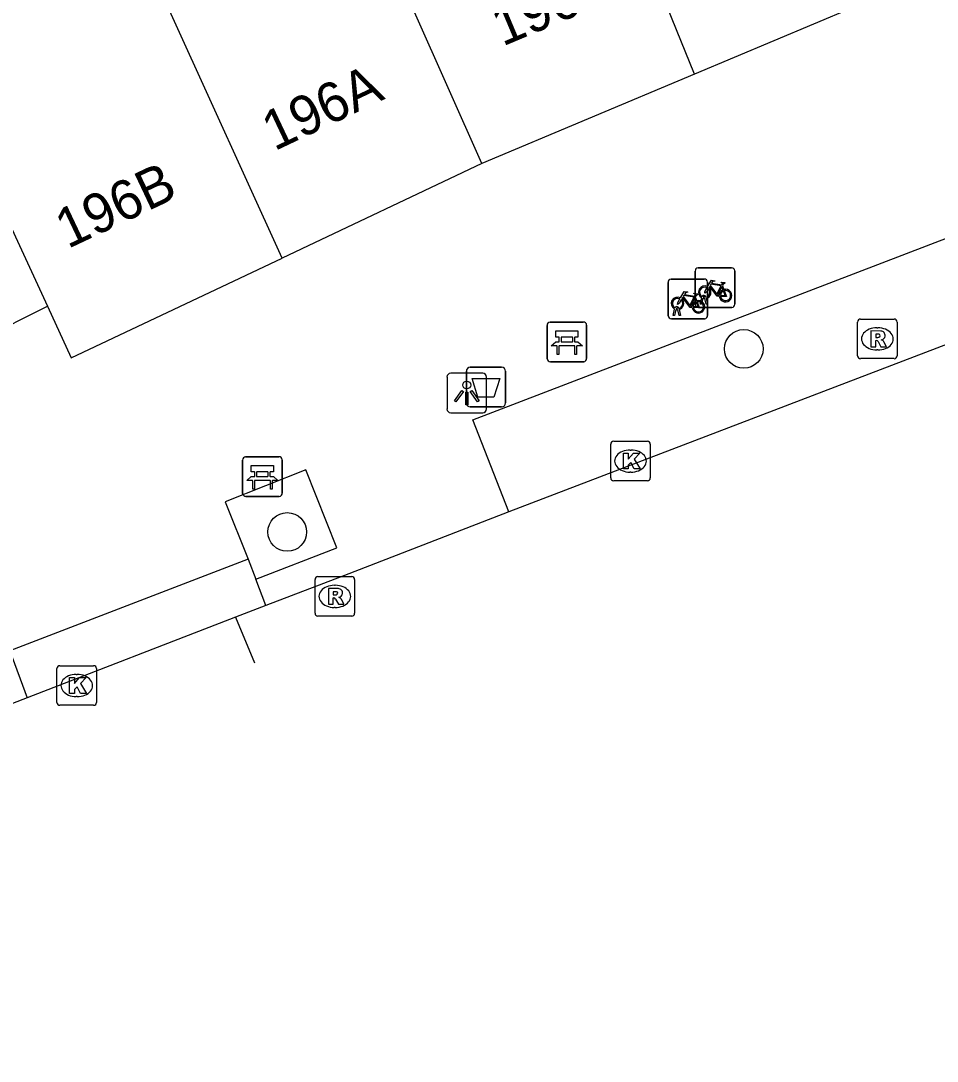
# Model space of a CAD drawing. Extents: x 159265 to 160143, y 383413 to 384319.
# Drawn here: x 159613.82 to 159636.98, y 383551.19 to 383577.48 of the extents above; entities that cross this region are included whole.
import ezdxf

# ---------------------------------------------------------------- set-up
doc = ezdxf.new("R2010")
doc.units = 0
for name, color, linetype in [('IMGEO_Afvalbak', 7, 'Continuous'), ('IMGEO_Bank', 7, 'Continuous'), ('IMGEO_Boom', 7, 'Continuous'), ('IMGEO_Fietsenrek', 7, 'Continuous'), ('IMGEO_Kolk', 7, 'Continuous'), ('IMGEO_Lichtpunt', 7, 'Continuous'), ('IMGEO_Pand', 7, 'Continuous'), ('IMGEO_Pand_nummerreeks', 7, 'Continuous'), ('IMGEO_Rijbaan_lokaal_gesloten', 7, 'Continuous'), ('IMGEO_Rijbaan_lokaal_open', 7, 'Continuous'), ('IMGEO_Rioolput', 7, 'Continuous'), ('IMGEO_Voetpad_open', 7, 'Continuous')]:
    doc.layers.add(name, color=color, linetype=linetype)

msp = doc.modelspace()

# ---------------------------------------------------------------- linework, layer by layer
at = {"layer": 'IMGEO_Afvalbak'}
for p, q in [((159625.079, 383567.826), (159625.079, 383568.626)), ((159625.079, 383568.626), (159625.079, 383567.826)), ((159625.179, 383568.726), (159625.969, 383568.726)), ((159625.969, 383568.726), (159625.179, 383568.726)), ((159626.069, 383568.626), (159626.069, 383567.826)), ((159626.069, 383567.826), (159626.069, 383568.626)), ((159625.969, 383567.726), (159625.179, 383567.726)), ((159625.179, 383567.726), (159625.969, 383567.726))]:
    msp.add_line(p, q, dxfattribs=at)
msp.add_lwpolyline([(159625.222, 383568.44), (159625.926, 383568.44), (159625.777, 383567.97), (159625.371, 383567.97), (159625.222, 383568.44)], dxfattribs=at)
for centre, start, end in [((159625.179, 383568.626), 90, 180), ((159625.179, 383568.626), 90, 180), ((159625.969, 383568.626), 0, 90), ((159625.969, 383568.626), 360, 90), ((159625.179, 383567.826), 180, 270), ((159625.179, 383567.826), 180, 270), ((159625.969, 383567.826), 270, 0), ((159625.969, 383567.826), 270, 0)]:
    msp.add_arc(centre, 0.1, start, end, dxfattribs=at)
at = {"layer": 'IMGEO_Bank'}
for p, q in [((159627.12, 383568.942), (159627.12, 383569.783)), ((159627.12, 383569.783), (159627.12, 383568.942)), ((159627.195, 383569.867), (159628.036, 383569.867)), ((159628.036, 383569.867), (159627.195, 383569.867)), ((159628.12, 383569.792), (159628.12, 383568.951)), ((159628.12, 383568.951), (159628.12, 383569.792)), ((159627.429, 383569.373), (159627.429, 383569.479)), ((159627.473, 383569.479), (159627.473, 383569.373)), ((159627.761, 383569.485), (159627.479, 383569.485)), ((159627.767, 383569.373), (159627.767, 383569.479)), ((159627.811, 383569.479), (159627.811, 383569.373)), ((159627.817, 383569.265), (159627.424, 383569.265)), ((159627.479, 383569.367), (159627.761, 383569.367)), ((159628.045, 383568.867), (159627.204, 383568.867)), ((159627.204, 383568.867), (159628.045, 383568.867)), ((159619.424, 383565.538), (159619.424, 383566.379)), ((159619.424, 383566.379), (159619.424, 383565.538)), ((159619.499, 383566.463), (159620.34, 383566.463)), ((159620.34, 383566.463), (159619.499, 383566.463)), ((159620.424, 383566.388), (159620.424, 383565.547)), ((159620.424, 383565.547), (159620.424, 383566.388)), ((159619.733, 383565.969), (159619.733, 383566.075)), ((159619.777, 383566.075), (159619.777, 383565.969)), ((159620.065, 383566.081), (159619.783, 383566.081)), ((159619.783, 383565.963), (159620.065, 383565.963)), ((159620.071, 383565.969), (159620.071, 383566.075)), ((159620.115, 383566.075), (159620.115, 383565.969)), ((159620.121, 383565.861), (159619.728, 383565.861)), ((159620.349, 383565.463), (159619.508, 383565.463)), ((159619.508, 383565.463), (159620.349, 383565.463))]:
    msp.add_line(p, q, dxfattribs=at)
for points in [[(159627.423, 383569.485), (159627.337, 383569.485), (159627.337, 383569.646), (159627.9, 383569.646), (159627.9, 383569.485), (159627.817, 383569.485)], [(159627.367, 383569.265), (159627.225, 383569.265), (159627.337, 383569.367), (159627.423, 383569.367)], [(159627.417, 383569.258), (159627.417, 383569.051), (159627.374, 383569.051), (159627.374, 383569.258)], [(159627.817, 383569.367), (159627.9, 383569.367), (159628.012, 383569.265), (159627.873, 383569.265)], [(159627.867, 383569.258), (159627.867, 383569.051), (159627.823, 383569.051), (159627.823, 383569.258)], [(159619.727, 383566.081), (159619.641, 383566.081), (159619.641, 383566.242), (159620.204, 383566.242), (159620.204, 383566.081), (159620.121, 383566.081)], [(159619.671, 383565.861), (159619.529, 383565.861), (159619.641, 383565.963), (159619.727, 383565.963)], [(159620.121, 383565.963), (159620.204, 383565.963), (159620.316, 383565.861), (159620.177, 383565.861)], [(159619.721, 383565.854), (159619.721, 383565.647), (159619.678, 383565.647), (159619.678, 383565.854)], [(159620.171, 383565.854), (159620.171, 383565.647), (159620.127, 383565.647), (159620.127, 383565.854)]]:
    msp.add_lwpolyline(points, dxfattribs=at)
for centre, radius, start, end in [((159627.198, 383569.789), 0.0779, 92.4484, 184.2845), ((159627.198, 383569.789), 0.0779, 92.4484, 184.2845), ((159628.042, 383569.789), 0.0779, 2.4484, 94.2845), ((159628.042, 383569.789), 0.0779, 2.4484, 94.2845), ((159627.422, 383569.478), 0.00671, 2.8957, 87.1043), ((159627.422, 383569.374), 0.00671, 272.8957, 357.1043), ((159627.479, 383569.478), 0.00671, 92.8957, 177.1043), ((159627.479, 383569.374), 0.00671, 182.8957, 267.1043), ((159627.761, 383569.478), 0.00671, 2.8957, 87.1043), ((159627.761, 383569.374), 0.00671, 272.8957, 357.1043), ((159627.818, 383569.478), 0.00671, 92.8957, 177.1043), ((159627.818, 383569.374), 0.00671, 182.8957, 267.1043), ((159627.367, 383569.258), 0.00671, 2.8957, 87.1043), ((159627.424, 383569.258), 0.00671, 92.8957, 177.1043), ((159627.816, 383569.258), 0.00671, 2.8957, 87.1043), ((159627.873, 383569.258), 0.00671, 92.8957, 177.1043), ((159627.198, 383568.945), 0.0779, 182.4484, 274.2845), ((159627.198, 383568.945), 0.0779, 182.4484, 274.2845), ((159628.042, 383568.945), 0.0779, 272.4484, 4.2845), ((159628.042, 383568.945), 0.0779, 272.4484, 4.2845), ((159619.502, 383566.385), 0.0779, 92.4484, 184.2845), ((159619.502, 383566.385), 0.0779, 92.4484, 184.2845), ((159620.346, 383566.385), 0.0779, 2.4484, 94.2845), ((159620.346, 383566.385), 0.0779, 2.4484, 94.2845), ((159619.726, 383566.074), 0.00671, 2.8957, 87.1043), ((159619.726, 383565.97), 0.00671, 272.8957, 357.1043), ((159619.783, 383566.074), 0.00671, 92.8957, 177.1043), ((159619.783, 383565.97), 0.00671, 182.8957, 267.1043), ((159620.065, 383566.074), 0.00671, 2.8957, 87.1043), ((159620.065, 383565.97), 0.00671, 272.8957, 357.1043), ((159620.122, 383566.074), 0.00671, 92.8957, 177.1043), ((159620.122, 383565.97), 0.00671, 182.8957, 267.1043), ((159619.671, 383565.854), 0.00671, 2.8957, 87.1043), ((159619.728, 383565.854), 0.00671, 92.8957, 177.1043), ((159620.12, 383565.854), 0.00671, 2.8957, 87.1043), ((159620.177, 383565.854), 0.00671, 92.8957, 177.1043), ((159619.502, 383565.541), 0.0779, 182.4484, 274.2845), ((159619.502, 383565.541), 0.0779, 182.4484, 274.2845), ((159620.346, 383565.541), 0.0779, 272.4484, 4.2845), ((159620.346, 383565.541), 0.0779, 272.4484, 4.2845)]:
    msp.add_arc(centre, radius, start, end, dxfattribs=at)
at = {"layer": 'IMGEO_Boom'}
for centre in [(159632.092, 383569.191), (159620.551, 383564.563)]:
    msp.add_circle(centre, 0.489, dxfattribs=at)
at = {"layer": 'IMGEO_Fietsenrek'}
for p, q in [((159630.939, 383571.238), (159631.78, 383571.238)), ((159631.78, 383571.238), (159630.939, 383571.238)), ((159630.253, 383570.954), (159631.094, 383570.954)), ((159631.094, 383570.954), (159630.253, 383570.954)), ((159630.864, 383570.313), (159630.864, 383571.154)), ((159630.864, 383571.154), (159630.864, 383570.313)), ((159631.864, 383571.163), (159631.864, 383570.322)), ((159631.864, 383570.322), (159631.864, 383571.163)), ((159630.178, 383570.029), (159630.178, 383570.87)), ((159630.178, 383570.87), (159630.178, 383570.029)), ((159631.178, 383570.879), (159631.178, 383570.038)), ((159631.178, 383570.038), (159631.178, 383570.879)), ((159631.551, 383570.787), (159631.587, 383570.692)), ((159630.865, 383570.503), (159630.901, 383570.408)), ((159630.991, 383570.322), (159631.03, 383570.482)), ((159631.06, 383570.47), (159631.025, 383570.322)), ((159631.102, 383570.494), (159631.101, 383570.498)), ((159631.143, 383570.322), (159631.109, 383570.464)), ((159631.133, 383570.505), (159631.134, 383570.498)), ((159631.141, 383570.468), (159631.176, 383570.322)), ((159630.305, 383570.038), (159630.344, 383570.198)), ((159630.374, 383570.186), (159630.339, 383570.038)), ((159630.416, 383570.21), (159630.415, 383570.214)), ((159630.457, 383570.038), (159630.423, 383570.18)), ((159630.447, 383570.221), (159630.448, 383570.214)), ((159630.455, 383570.184), (159630.49, 383570.038)), ((159631.789, 383570.238), (159630.948, 383570.238)), ((159630.948, 383570.238), (159631.789, 383570.238)), ((159631.025, 383570.322), (159630.991, 383570.322)), ((159631.176, 383570.322), (159631.143, 383570.322)), ((159631.103, 383569.954), (159630.262, 383569.954)), ((159630.262, 383569.954), (159631.103, 383569.954)), ((159630.339, 383570.038), (159630.305, 383570.038)), ((159630.49, 383570.038), (159630.457, 383570.038))]:
    msp.add_line(p, q, dxfattribs=at)
for points in [[(159631.198, 383570.712), (159631.146, 383570.622), (159631.106, 383570.597), (159631.107, 383570.644), (159631.162, 383570.738)], [(159631.177, 383570.764), (159631.272, 383570.928), (159631.358, 383570.914), (159631.36, 383570.905), (159631.304, 383570.894), (159631.277, 383570.849), (159631.533, 383570.808)], [(159631.473, 383570.52), (159631.423, 383570.52), (159631.232, 383570.771), (159631.213, 383570.739)], [(159631.52, 383570.783), (159631.263, 383570.824), (159631.246, 383570.795), (159631.413, 383570.575), (159631.52, 383570.783)], [(159631.568, 383570.685), (159631.538, 383570.762), (159631.429, 383570.544), (159631.472, 383570.544)], [(159631.533, 383570.808), (159631.558, 383570.857), (159631.552, 383570.861), (159631.529, 383570.865), (159631.517, 383570.872), (159631.516, 383570.875), (159631.518, 383570.88), (159631.613, 383570.865), (159631.615, 383570.855), (159631.605, 383570.842), (159631.593, 383570.836), (159631.579, 383570.842), (159631.551, 383570.787)], [(159630.512, 383570.428), (159630.46, 383570.338), (159630.42, 383570.313), (159630.421, 383570.36), (159630.476, 383570.454)], [(159630.491, 383570.48), (159630.586, 383570.644), (159630.672, 383570.63), (159630.674, 383570.621), (159630.618, 383570.61), (159630.591, 383570.565), (159630.847, 383570.524)], [(159630.787, 383570.236), (159630.737, 383570.236), (159630.546, 383570.487), (159630.527, 383570.455)], [(159630.834, 383570.499), (159630.577, 383570.54), (159630.56, 383570.511), (159630.727, 383570.291), (159630.834, 383570.499)], [(159630.882, 383570.401), (159630.852, 383570.478), (159630.743, 383570.26), (159630.786, 383570.26)], [(159630.847, 383570.524), (159630.872, 383570.573), (159630.866, 383570.577), (159630.843, 383570.581), (159630.831, 383570.588), (159630.83, 383570.591), (159630.832, 383570.596), (159630.927, 383570.581), (159630.929, 383570.571), (159630.919, 383570.558), (159630.907, 383570.552), (159630.893, 383570.558), (159630.865, 383570.503)], [(159631.502, 383570.544), (159631.622, 383570.543), (159631.578, 383570.657)], [(159631.598, 383570.664), (159631.653, 383570.519), (159631.503, 383570.519)], [(159630.816, 383570.26), (159630.936, 383570.259), (159630.892, 383570.373)], [(159630.912, 383570.38), (159630.967, 383570.235), (159630.817, 383570.235)]]:
    msp.add_lwpolyline(points, dxfattribs=at)
for centre, radius, start, end in [((159630.942, 383571.16), 0.0779, 92.4484, 184.2845), ((159630.942, 383571.16), 0.0779, 92.4484, 184.2845), ((159631.786, 383571.16), 0.0779, 2.4484, 94.2845), ((159631.786, 383571.16), 0.0779, 2.4484, 94.2845), ((159630.256, 383570.876), 0.0779, 92.4484, 184.2845), ((159630.256, 383570.876), 0.0779, 92.4484, 184.2845), ((159631.1, 383570.876), 0.0779, 2.4484, 94.2845), ((159631.1, 383570.876), 0.0779, 2.4484, 94.2845), ((159631.104, 383570.623), 0.159, 62.6766, 242.1369), ((159631.104, 383570.623), 0.129, 63.3192, 238.903), ((159631.104, 383570.623), 0.129, 283.6043, 43.4302), ((159631.104, 383570.623), 0.159, 283.5766, 46.6042), ((159631.631, 383570.539), 0.159, 187.0065, 105.7708), ((159630.418, 383570.339), 0.159, 62.6766, 242.1369), ((159630.418, 383570.339), 0.129, 63.3192, 238.903), ((159630.418, 383570.339), 0.129, 283.6043, 43.4302), ((159630.418, 383570.339), 0.159, 283.5766, 46.6042), ((159631.084, 383570.494), 0.0499, 12.8025, 158.6934), ((159631.104, 383570.623), 0.159, 253.9967, 271.7867), ((159631.084, 383570.494), 0.0174, 12.8025, 163.4502), ((159631.104, 383570.623), 0.129, 253.415, 269.0204), ((159631.631, 383570.539), 0.159, 113.3408, 178.3217), ((159631.631, 383570.539), 0.129, 113.923, 177.9556), ((159631.631, 383570.539), 0.129, 188.6715, 104.5883), ((159630.398, 383570.21), 0.0499, 12.8025, 158.6934), ((159630.418, 383570.339), 0.159, 253.9967, 271.7867), ((159630.398, 383570.21), 0.0174, 12.8025, 163.4502), ((159630.418, 383570.339), 0.129, 253.415, 269.0204), ((159630.945, 383570.255), 0.159, 113.3408, 178.3217), ((159630.945, 383570.255), 0.159, 187.0065, 105.7708), ((159630.945, 383570.255), 0.129, 113.923, 177.9556), ((159630.945, 383570.255), 0.129, 188.6715, 104.5883), ((159630.942, 383570.316), 0.0779, 182.4484, 274.2845), ((159630.942, 383570.316), 0.0779, 182.4484, 274.2845), ((159631.786, 383570.316), 0.0779, 272.4484, 4.2845), ((159631.786, 383570.316), 0.0779, 272.4484, 4.2845), ((159630.256, 383570.032), 0.0779, 182.4484, 274.2845), ((159630.256, 383570.032), 0.0779, 182.4484, 274.2845), ((159631.1, 383570.032), 0.0779, 272.4484, 4.2845), ((159631.1, 383570.032), 0.0779, 272.4484, 4.2845)]:
    msp.add_arc(centre, radius, start, end, dxfattribs=at)
at = {"layer": 'IMGEO_Kolk'}
for p, q in [((159628.728, 383565.929), (159628.728, 383566.781)), ((159628.803, 383566.855), (159629.655, 383566.855)), ((159629.729, 383566.781), (159629.729, 383565.929)), ((159629.216, 383566.635), (159629.241, 383566.635)), ((159629.239, 383566.075), (159629.214, 383566.075)), ((159629.655, 383565.855), (159628.803, 383565.855)), ((159614.73, 383560.256), (159614.73, 383561.108)), ((159614.805, 383561.182), (159615.657, 383561.182)), ((159615.218, 383560.962), (159615.243, 383560.962)), ((159615.731, 383561.108), (159615.731, 383560.256)), ((159615.657, 383560.182), (159614.805, 383560.182)), ((159615.241, 383560.402), (159615.216, 383560.402))]:
    msp.add_line(p, q, dxfattribs=at)
for points in [[(159628.728, 383565.929), (159628.728, 383566.781)], [(159628.803, 383566.855), (159629.655, 383566.855)], [(159629.729, 383566.781), (159629.729, 383565.929)], [(159629.049, 383566.555), (159629.172, 383566.555), (159629.172, 383566.404), (159629.302, 383566.555), (159629.466, 383566.555), (159629.32, 383566.404), (159629.473, 383566.155), (159629.321, 383566.155), (159629.236, 383566.319), (159629.172, 383566.252), (159629.172, 383566.155), (159629.049, 383566.155), (159629.049, 383566.555)], [(159629.655, 383565.855), (159628.803, 383565.855)], [(159614.73, 383560.256), (159614.73, 383561.108)], [(159614.805, 383561.182), (159615.657, 383561.182)], [(159615.731, 383561.108), (159615.731, 383560.256)], [(159615.051, 383560.882), (159615.174, 383560.882), (159615.174, 383560.731), (159615.304, 383560.882), (159615.468, 383560.882), (159615.322, 383560.731), (159615.475, 383560.482), (159615.323, 383560.482), (159615.238, 383560.646), (159615.174, 383560.579), (159615.174, 383560.482), (159615.051, 383560.482), (159615.051, 383560.882)], [(159615.657, 383560.182), (159614.805, 383560.182)]]:
    msp.add_lwpolyline(points, dxfattribs=at)
for centre, start, end in [((159628.805, 383566.779), 91.552, 178.448), ((159628.805, 383566.779), 91.552, 178.448), ((159629.653, 383566.779), 1.552, 88.448), ((159629.653, 383566.779), 1.552, 88.448), ((159628.805, 383565.931), 181.552, 268.448), ((159628.805, 383565.931), 181.552, 268.448), ((159629.653, 383565.931), 271.552, 358.448), ((159629.653, 383565.931), 271.552, 358.448), ((159614.807, 383561.106), 91.552, 178.448), ((159614.807, 383561.106), 91.552, 178.448), ((159615.655, 383561.106), 1.552, 88.448), ((159615.655, 383561.106), 1.552, 88.448), ((159614.807, 383560.258), 181.552, 268.448), ((159614.807, 383560.258), 181.552, 268.448), ((159615.655, 383560.258), 271.552, 358.448), ((159615.655, 383560.258), 271.552, 358.448)]:
    msp.add_arc(centre, 0.0765, start, end, dxfattribs=at)
for centre, major_axis, ratio, start_param, end_param in [((159629.215, 383566.355), (-0.387, 0.002), 0.722429, 4.712389, 7.853982), ((159629.24, 383566.355), (-0.39, 0.002), 0.717154, 1.570796, 4.712389), ((159615.217, 383560.682), (-0.387, 0.002), 0.722429, 4.712389, 7.853982), ((159615.242, 383560.682), (-0.39, 0.002), 0.717154, 1.570796, 4.712389)]:
    msp.add_ellipse(centre, major_axis=major_axis, ratio=ratio, start_param=start_param, end_param=end_param, dxfattribs=at)
at = {"layer": 'IMGEO_Lichtpunt'}
for p, q in [((159624.59, 383568.479), (159624.59, 383567.672)), ((159624.59, 383568.479), (159624.59, 383567.672)), ((159625.492, 383568.574), (159624.684, 383568.574)), ((159625.492, 383568.574), (159624.684, 383568.574)), ((159625.586, 383567.672), (159625.586, 383568.479)), ((159625.586, 383567.672), (159625.586, 383568.479)), ((159624.684, 383567.578), (159625.492, 383567.578)), ((159624.684, 383567.578), (159625.492, 383567.578))]:
    msp.add_line(p, q, dxfattribs=at)
for points in [[(159624.964, 383568.143), (159625.003, 383568.115), (159624.815, 383567.853), (159624.777, 383567.88), (159624.964, 383568.143)], [(159625.066, 383568.095), (159625.113, 383568.095), (159625.113, 383567.773), (159625.066, 383567.773), (159625.066, 383568.095)], [(159625.176, 383568.115), (159625.214, 383568.142), (159625.401, 383567.88), (159625.362, 383567.852), (159625.176, 383568.115)]]:
    msp.add_lwpolyline(points, dxfattribs=at)
msp.add_circle((159625.089, 383568.277), 0.0994, dxfattribs=at)
for centre, start, end in [((159624.684, 383568.479), 90, 180), ((159624.684, 383568.479), 90, 180), ((159625.492, 383568.479), 0, 90), ((159625.492, 383568.479), 0, 90), ((159624.684, 383567.672), 180, 270), ((159624.684, 383567.672), 180, 270), ((159625.492, 383567.672), 270, 0), ((159625.492, 383567.672), 270, 360)]:
    msp.add_arc(centre, 0.0946, start, end, dxfattribs=at)
at = {"layer": 'IMGEO_Pand'}
for points in [[(159608.659, 383597.35), (159604.887, 383595.655), (159609.507, 383581.069), (159614.49, 383570.268)], [(159625.472, 383573.875), (159622.03, 383581.613), (159617.946, 383591.184)], [(159620.423, 383571.487), (159614.977, 383583.46), (159612.61, 383588.664)], [(159630.844, 383576.135), (159625.844, 383588.47)], [(159636.253, 383578.389), (159635.861, 383578.246), (159630.844, 383576.135)], [(159630.844, 383576.135), (159625.472, 383573.875)], [(159625.472, 383573.875), (159620.423, 383571.487)], [(159614.49, 383570.268), (159615.091, 383568.965), (159620.423, 383571.487)]]:
    msp.add_lwpolyline(points, dxfattribs=at)
at = {"layer": 'IMGEO_Rijbaan_lokaal_gesloten'}
for points in [[(159619.247, 383562.409), (159613.978, 383560.368)], [(159619.247, 383562.409), (159619.725, 383561.254)], [(159613.978, 383560.368), (159590.237, 383551.186)]]:
    msp.add_lwpolyline(points, dxfattribs=at)
at = {"layer": 'IMGEO_Rijbaan_lokaal_open'}
for points in [[(159644.929, 383572.251), (159626.149, 383565.073)], [(159611.199, 383568.622), (159614.49, 383570.268)], [(159626.149, 383565.073), (159622.105, 383563.501), (159620.012, 383562.705)], [(159620.012, 383562.705), (159619.247, 383562.409)]]:
    msp.add_lwpolyline(points, dxfattribs=at)
at = {"layer": 'IMGEO_Rioolput'}
for p, q in [((159635.043, 383569.944), (159635.895, 383569.944)), ((159634.968, 383569.018), (159634.968, 383569.87)), ((159635.456, 383569.724), (159635.481, 383569.724)), ((159635.969, 383569.87), (159635.969, 383569.018)), ((159635.479, 383569.164), (159635.454, 383569.164)), ((159635.895, 383568.944), (159635.043, 383568.944)), ((159621.254, 383562.509), (159621.254, 383563.361)), ((159621.329, 383563.435), (159622.181, 383563.435)), ((159622.255, 383563.361), (159622.255, 383562.509)), ((159621.742, 383563.215), (159621.767, 383563.215)), ((159621.765, 383562.655), (159621.74, 383562.655)), ((159622.181, 383562.435), (159621.329, 383562.435))]:
    msp.add_line(p, q, dxfattribs=at)
for points in [[(159635.043, 383569.944), (159635.895, 383569.944)], [(159634.968, 383569.018), (159634.968, 383569.87)], [(159635.557, 383569.642), (159635.305, 383569.644), (159635.305, 383569.244)], [(159635.969, 383569.87), (159635.969, 383569.018)], [(159635.305, 383569.244), (159635.429, 383569.244), (159635.429, 383569.406), (159635.44, 383569.406)], [(159635.483, 383569.563), (159635.429, 383569.563), (159635.429, 383569.482)], [(159635.429, 383569.482), (159635.481, 383569.482)], [(159635.487, 383569.377), (159635.558, 383569.244), (159635.698, 383569.244), (159635.633, 383569.37)], [(159635.895, 383568.944), (159635.043, 383568.944)], [(159621.254, 383562.509), (159621.254, 383563.361)], [(159621.329, 383563.435), (159622.181, 383563.435)], [(159622.255, 383563.361), (159622.255, 383562.509)], [(159621.843, 383563.133), (159621.591, 383563.135), (159621.591, 383562.735)], [(159621.591, 383562.735), (159621.715, 383562.735), (159621.715, 383562.897), (159621.726, 383562.897)], [(159621.769, 383563.054), (159621.715, 383563.054), (159621.715, 383562.973)], [(159621.715, 383562.973), (159621.767, 383562.973)], [(159621.773, 383562.868), (159621.844, 383562.735), (159621.984, 383562.735), (159621.919, 383562.861)], [(159622.181, 383562.435), (159621.329, 383562.435)]]:
    msp.add_lwpolyline(points, dxfattribs=at)
for centre, radius, start, end in [((159635.045, 383569.868), 0.0765, 91.552, 178.448), ((159635.045, 383569.868), 0.0765, 91.552, 178.448), ((159635.893, 383569.868), 0.0765, 1.552, 88.448), ((159635.893, 383569.868), 0.0765, 1.552, 88.448), ((159635.556, 383569.532), 0.109, 350.3612, 89.416), ((159635.439, 383569.353), 0.0533, 26.0293, 88.6989), ((159635.465, 383569.671), 0.19, 274.7715, 282.9687), ((159635.489, 383569.467), 0.0964, 77.0061, 93.1865), ((159635.503, 383569.524), 0.0378, 276.6634, 79.6772), ((159635.554, 383569.532), 0.112, 277.5842, 350.9817), ((159635.538, 383569.317), 0.108, 29.5134, 73.7905), ((159635.045, 383569.02), 0.0765, 181.552, 268.448), ((159635.045, 383569.02), 0.0765, 181.552, 268.448), ((159635.893, 383569.02), 0.0765, 271.552, 358.448), ((159635.893, 383569.02), 0.0765, 271.552, 358.448), ((159621.331, 383563.359), 0.0765, 91.552, 178.448), ((159621.331, 383563.359), 0.0765, 91.552, 178.448), ((159622.179, 383563.359), 0.0765, 1.552, 88.448), ((159622.179, 383563.359), 0.0765, 1.552, 88.448), ((159621.842, 383563.023), 0.109, 350.3612, 89.416), ((159621.725, 383562.844), 0.0533, 26.0293, 88.6989), ((159621.751, 383563.162), 0.19, 274.7715, 282.9687), ((159621.775, 383562.958), 0.0964, 77.0061, 93.1865), ((159621.789, 383563.015), 0.0378, 276.6634, 79.6772), ((159621.84, 383563.023), 0.112, 277.5842, 350.9817), ((159621.824, 383562.808), 0.108, 29.5134, 73.7905), ((159621.331, 383562.511), 0.0765, 181.552, 268.448), ((159621.331, 383562.511), 0.0765, 181.552, 268.448), ((159622.179, 383562.511), 0.0765, 271.552, 358.448), ((159622.179, 383562.511), 0.0765, 271.552, 358.448)]:
    msp.add_arc(centre, radius, start, end, dxfattribs=at)
for centre, major_axis, ratio, start_param, end_param in [((159635.455, 383569.444), (-0.387, 0.002), 0.722429, 4.712389, 7.853982), ((159635.48, 383569.444), (-0.39, 0.002), 0.717154, 1.570796, 4.712389), ((159621.741, 383562.935), (-0.387, 0.002), 0.722429, 4.712389, 7.853982), ((159621.766, 383562.935), (-0.39, 0.002), 0.717154, 1.570796, 4.712389)]:
    msp.add_ellipse(centre, major_axis=major_axis, ratio=ratio, start_param=start_param, end_param=end_param, dxfattribs=at)
at = {"layer": 'IMGEO_Voetpad_open'}
for points in [[(159626.149, 383565.073), (159625.245, 383567.397), (159643.978, 383574.584)], [(159619.757, 383563.373), (159621.805, 383564.165), (159621.022, 383566.13), (159618.982, 383565.321), (159619.566, 383563.872)], [(159619.566, 383563.872), (159613.538, 383561.556)], [(159619.566, 383563.872), (159619.757, 383563.373)], [(159620.012, 383562.705), (159619.757, 383563.373)], [(159613.538, 383561.556), (159613.978, 383560.368)]]:
    msp.add_lwpolyline(points, dxfattribs=at)

# ---------------------------------------------------------------- texts
at = {"layer": 'IMGEO_Pand_nummerreeks'}
for s, rotation, p in [('196', 22.8209, (159625.993, 383576.829)), ('196A', 25.3148, (159620.226, 383574.182)), ('196B', 25.317, (159615.003, 383571.711))]:
    msp.add_text(s, height=1, rotation=rotation, dxfattribs=at).set_placement(p)

doc.saveas('drawing.dxf')
